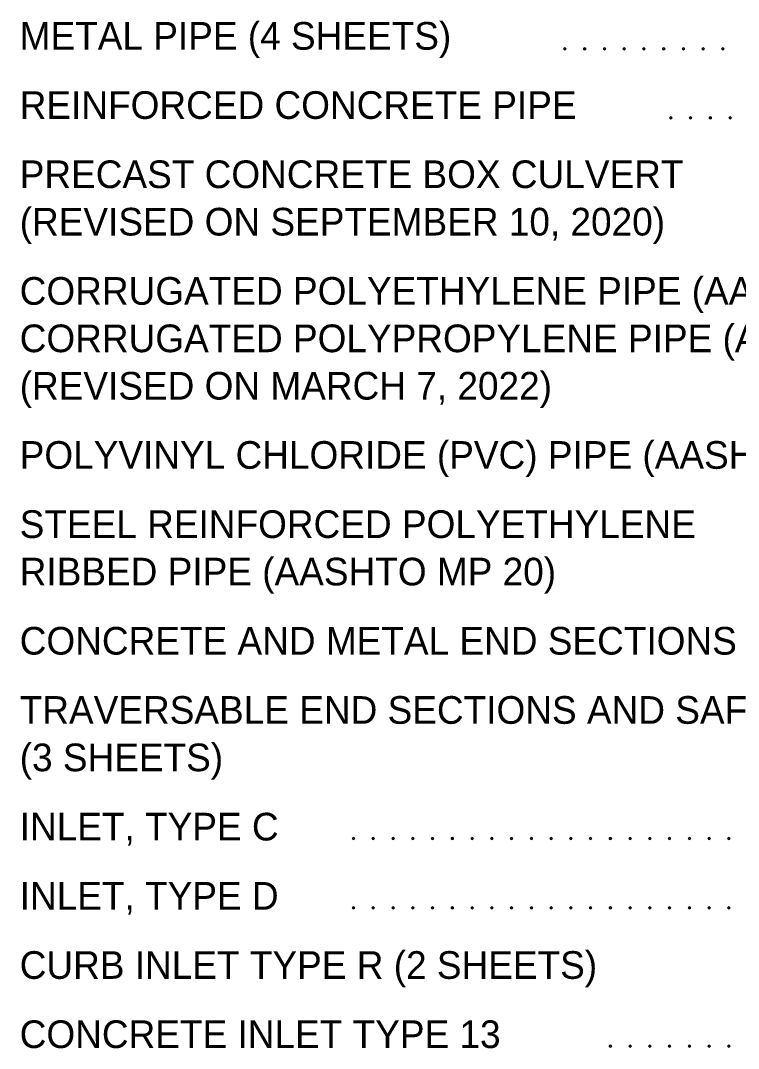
# Model space of a CAD drawing. Extents: x 0 to 1.42, y 0 to 0.92.
# Drawn here: x 0.1862 to 0.3377, y 0.2395 to 0.4562 of the extents above; entities that cross this region are included whole.
import ezdxf

# ---------------------------------------------------------------- set-up
doc = ezdxf.new("R2010")
doc.units = 0
doc.layers.add('DRAFT_Text-Notes', color=7, linetype='Continuous')
doc.layers.add('DRAFT_Text-Titles', color=7, linetype='Continuous')

msp = doc.modelspace()

# ---------------------------------------------------------------- linework, layer by layer
at = {"layer": 'DRAFT_Text-Notes'}
for centre in [(0.30106, 0.45026), (0.30522, 0.45026), (0.30939, 0.45026), (0.31356, 0.45026), (0.31772, 0.45026), (0.32189, 0.45026), (0.32606, 0.45026), (0.33022, 0.45026), (0.33439, 0.45026), (0.3234, 0.43567), (0.32756, 0.43567), (0.33173, 0.43567), (0.3359, 0.43567), (0.25648, 0.28372), (0.26064, 0.28372), (0.26481, 0.28372), (0.26898, 0.28372), (0.27314, 0.28372), (0.27731, 0.28372), (0.28148, 0.28372), (0.28564, 0.28372), (0.28981, 0.28372), (0.29398, 0.28372), (0.29814, 0.28372), (0.30231, 0.28372), (0.30648, 0.28372), (0.31064, 0.28372), (0.31481, 0.28372), (0.31898, 0.28372), (0.32314, 0.28372), (0.32731, 0.28372), (0.33148, 0.28372), (0.33564, 0.28372), (0.25648, 0.26913), (0.26064, 0.26913), (0.26481, 0.26913), (0.26898, 0.26913), (0.27314, 0.26913), (0.27731, 0.26913), (0.28148, 0.26913), (0.28564, 0.26913), (0.28981, 0.26913), (0.29398, 0.26913), (0.29814, 0.26913), (0.30231, 0.26913), (0.30648, 0.26913), (0.31064, 0.26913), (0.31481, 0.26913), (0.31898, 0.26913), (0.32314, 0.26913), (0.32731, 0.26913), (0.33148, 0.26913), (0.33564, 0.26913), (0.31064, 0.23994), (0.31481, 0.23994), (0.31898, 0.23994), (0.32314, 0.23994), (0.32731, 0.23994), (0.33148, 0.23994), (0.33564, 0.23994)]:
    msp.add_circle(centre, 0.000208, dxfattribs=at)
for centre, start, end in [((0.30106, 0.45026), 0, 180), ((0.30106, 0.45026), 180, 0), ((0.30522, 0.45026), 0, 180), ((0.30522, 0.45026), 180, 0), ((0.30939, 0.45026), 0, 180), ((0.30939, 0.45026), 180, 0), ((0.31356, 0.45026), 0, 180), ((0.31356, 0.45026), 180, 0), ((0.31772, 0.45026), 0, 180), ((0.31772, 0.45026), 180, 0), ((0.32189, 0.45026), 0, 180), ((0.32189, 0.45026), 180, 0), ((0.32606, 0.45026), 0, 180), ((0.32606, 0.45026), 180, 0), ((0.33022, 0.45026), 0, 180), ((0.33022, 0.45026), 180, 0), ((0.33439, 0.45026), 0, 180), ((0.33439, 0.45026), 180, 0), ((0.3234, 0.43567), 0, 180), ((0.3234, 0.43567), 180, 0), ((0.32756, 0.43567), 0, 180), ((0.32756, 0.43567), 180, 0), ((0.33173, 0.43567), 0, 180), ((0.33173, 0.43567), 180, 0), ((0.3359, 0.43567), 0, 180), ((0.3359, 0.43567), 180, 0), ((0.25648, 0.28372), 0, 180), ((0.25648, 0.28372), 180, 0), ((0.26064, 0.28372), 0, 180), ((0.26064, 0.28372), 180, 0), ((0.26481, 0.28372), 0, 180), ((0.26481, 0.28372), 180, 0), ((0.26898, 0.28372), 0, 180), ((0.26898, 0.28372), 180, 0), ((0.27314, 0.28372), 0, 180), ((0.27314, 0.28372), 180, 0), ((0.27731, 0.28372), 0, 180), ((0.27731, 0.28372), 180, 0), ((0.28148, 0.28372), 0, 180), ((0.28148, 0.28372), 180, 0), ((0.28564, 0.28372), 0, 180), ((0.28564, 0.28372), 180, 0), ((0.28981, 0.28372), 0, 180), ((0.28981, 0.28372), 180, 0), ((0.29398, 0.28372), 0, 180), ((0.29398, 0.28372), 180, 0), ((0.29814, 0.28372), 0, 180), ((0.29814, 0.28372), 180, 0), ((0.30231, 0.28372), 0, 180), ((0.30231, 0.28372), 180, 0), ((0.30648, 0.28372), 0, 180), ((0.30648, 0.28372), 180, 0), ((0.31064, 0.28372), 0, 180), ((0.31064, 0.28372), 180, 0), ((0.31481, 0.28372), 0, 180), ((0.31481, 0.28372), 180, 0), ((0.31898, 0.28372), 0, 180), ((0.31898, 0.28372), 180, 0), ((0.32314, 0.28372), 0, 180), ((0.32314, 0.28372), 180, 0), ((0.32731, 0.28372), 0, 180), ((0.32731, 0.28372), 180, 0), ((0.33148, 0.28372), 0, 180), ((0.33148, 0.28372), 180, 0), ((0.33564, 0.28372), 0, 180), ((0.33564, 0.28372), 180, 0), ((0.25648, 0.26913), 0, 180), ((0.25648, 0.26913), 180, 0), ((0.26064, 0.26913), 0, 180), ((0.26064, 0.26913), 180, 0), ((0.26481, 0.26913), 0, 180), ((0.26481, 0.26913), 180, 0), ((0.26898, 0.26913), 0, 180), ((0.26898, 0.26913), 180, 0), ((0.27314, 0.26913), 0, 180), ((0.27314, 0.26913), 180, 0), ((0.27731, 0.26913), 0, 180), ((0.27731, 0.26913), 180, 0), ((0.28148, 0.26913), 0, 180), ((0.28148, 0.26913), 180, 0), ((0.28564, 0.26913), 0, 180), ((0.28564, 0.26913), 180, 0), ((0.28981, 0.26913), 0, 180), ((0.28981, 0.26913), 180, 0), ((0.29398, 0.26913), 0, 180), ((0.29398, 0.26913), 180, 0), ((0.29814, 0.26913), 0, 180), ((0.29814, 0.26913), 180, 0), ((0.30231, 0.26913), 0, 180), ((0.30231, 0.26913), 180, 0), ((0.30648, 0.26913), 0, 180), ((0.30648, 0.26913), 180, 0), ((0.31064, 0.26913), 0, 180), ((0.31064, 0.26913), 180, 0), ((0.31481, 0.26913), 0, 180), ((0.31481, 0.26913), 180, 0), ((0.31898, 0.26913), 0, 180), ((0.31898, 0.26913), 180, 0), ((0.32314, 0.26913), 0, 180), ((0.32314, 0.26913), 180, 0), ((0.32731, 0.26913), 0, 180), ((0.32731, 0.26913), 180, 0), ((0.33148, 0.26913), 0, 180), ((0.33148, 0.26913), 180, 0), ((0.33564, 0.26913), 0, 180), ((0.33564, 0.26913), 180, 0), ((0.31064, 0.23994), 0, 180), ((0.31064, 0.23994), 180, 0), ((0.31481, 0.23994), 0, 180), ((0.31481, 0.23994), 180, 0), ((0.31898, 0.23994), 0, 180), ((0.31898, 0.23994), 180, 0), ((0.32314, 0.23994), 0, 180), ((0.32314, 0.23994), 180, 0), ((0.32731, 0.23994), 0, 180), ((0.32731, 0.23994), 180, 0), ((0.33148, 0.23994), 0, 180), ((0.33148, 0.23994), 180, 0), ((0.33564, 0.23994), 0, 180), ((0.33564, 0.23994), 180, 0)]:
    msp.add_arc(centre, 0.000208, start, end, dxfattribs=at)

# ---------------------------------------------------------------- texts
for s, height, p in [('METAL PIPE (4 SHEETS)', 0.0058333, (0.18606, 0.45005)), ('REINFORCED CONCRETE PIPE', 0.0058333, (0.18606, 0.43546)), ('PRECAST CONCRETE BOX CULVERT', 0.0058333, (0.18606, 0.42087)), ('CORRUGATED POLYETHYLENE PIPE (AASHTO M294) AND', 0.0058333, (0.18606, 0.39627)), ('CORRUGATED POLYPROPYLENE PIPE (AASHTO M330) (2 sheets)', 0.0058333, (0.18606, 0.38627)), ('POLYVINYL CHLORIDE (PVC) PIPE (AASHTO M304)', 0.0058333, (0.18606, 0.36168)), ('STEEL REINFORCED POLYETHYLENE', 0.0058333, (0.18606, 0.34709)), ('RIBBED PIPE (AASHTO MP 20)', 0.0058333, (0.18606, 0.33709)), ('CONCRETE AND METAL END SECTIONS', 0.0058333, (0.18606, 0.3225)), ('TRAVERSABLE END SECTIONS AND SAFETY GRATES', 0.0058333, (0.18606, 0.30791)), ('(3 SHEETS)', 0.005833, (0.18606, 0.29791)), ('INLET, TYPE C', 0.0058333, (0.18606, 0.28331)), ('INLET, TYPE D', 0.0058333, (0.18606, 0.26872)), ('CURB INLET TYPE R (2 SHEETS)', 0.0058333, (0.18606, 0.25413)), ('CONCRETE INLET TYPE 13', 0.0058333, (0.18606, 0.23954))]:
    msp.add_text(s, height=height, dxfattribs=at).set_placement(p)
at = {"layer": 'DRAFT_Text-Titles'}
for s, p in [('(REVISED ON SEPTEMBER 10, 2020)', (0.18606, 0.41087)), ('(REVISED ON MARCH 7, 2022)', (0.18606, 0.37627))]:
    msp.add_text(s, height=0.0058333, dxfattribs=at).set_placement(p)

doc.saveas('drawing.dxf')
